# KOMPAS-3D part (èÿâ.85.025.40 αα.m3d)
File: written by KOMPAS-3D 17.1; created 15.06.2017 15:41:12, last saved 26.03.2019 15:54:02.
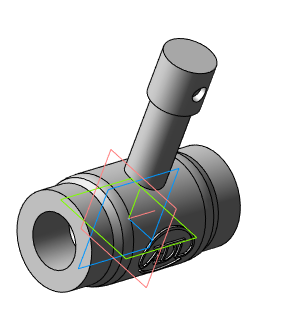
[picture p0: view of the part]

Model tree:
1. Операция без истории:2  (labels: Сталь 20  ГОСТ 1050-88)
